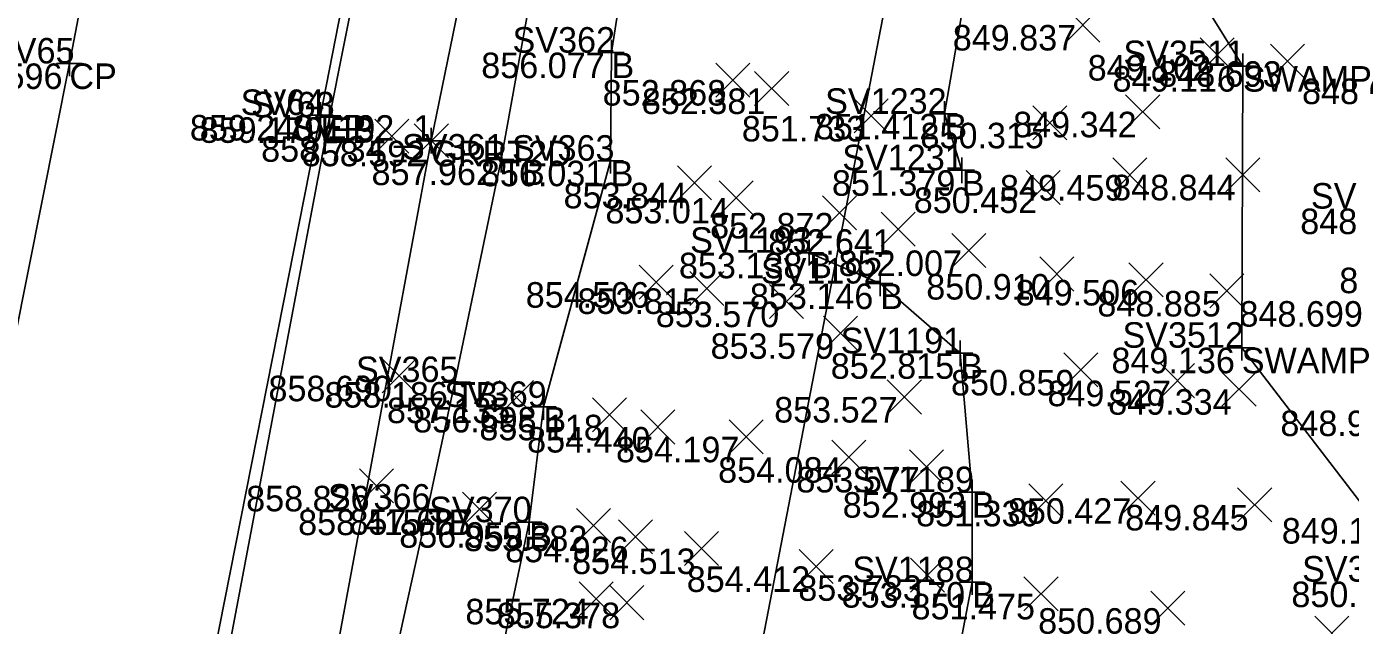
# Model space of a CAD drawing. Extents: x 2228183 to 2230895, y 679226 to 682223.
# Drawn here: x 2228291.3 to 2228343.2, y 680470.3 to 680493.8 of the extents above; entities that cross this region are included whole.
import ezdxf

# ---------------------------------------------------------------- set-up
doc = ezdxf.new("R2010")
doc.units = 0
for name, color, linetype in [('HY_X_Water_Edge', 7, 'Continuous'), ('PV_X_COP', 7, 'Continuous'), ('PV_X_EOP', 7, 'Continuous'), ('PV_X_Shoulder_Aggregate', 7, 'Continuous'), ('RD_X_GR_Rt', 7, 'Continuous'), ('SC_Scratch1', 7, 'Continuous'), ('SV_P_Control_Cells_Set', 7, 'Continuous'), ('SV_X_Break_Lines', 7, 'Continuous'), ('SV_X_Random_Point', 7, 'Continuous'), ('SV_X_Shot_Marker', 7, 'Continuous'), ('SV_X_Text_Comment', 7, 'Continuous'), ('SV_X_Top_of_Bank', 7, 'Continuous'), ('UT_X_Telecom', 7, 'Continuous')]:
    doc.layers.add(name, color=color, linetype=linetype)

msp = doc.modelspace()

# ---------------------------------------------------------------- linework, layer by layer
at = {"layer": 'HY_X_Water_Edge'}
msp.add_lwpolyline([(2228388.587, 680538.705), (2228381.654, 680540.428), (2228373.267, 680534.114), (2228362.534, 680538.041), (2228352.058, 680544.515), (2228344.28, 680554.272), (2228336.684, 680545.185), (2228336.291, 680530.248), (2228335.4, 680519.473), (2228335.533, 680511.573), (2228332.556, 680502.567), (2228338.972, 680492.245), (2228338.927, 680481.209), (2228345.953, 680472.044), (2228352.301, 680471.046)], dxfattribs=at)
at = {"layer": 'PV_X_COP'}
msp.add_lwpolyline([(2228262.604, 680193.524), (2228262.146, 680218.328), (2228262.437, 680243.717), (2228263.104, 680268.902), (2228264.443, 680294.535), (2228266.222, 680319.78), (2228268.589, 680344.685), (2228271.405, 680369.17), (2228274.939, 680394.252), (2228278.914, 680418.584), (2228283.486, 680443.605), (2228288.154, 680467.93), (2228293.014, 680492.349), (2228297.716, 680516.963), (2228302.55, 680541.357), (2228307.231, 680565.55), (2228311.972, 680589.697), (2228316.792, 680614.507), (2228321.818, 680639.234), (2228326.722, 680663.726), (2228331.754, 680688.345)], dxfattribs=at)
at = {"layer": 'PV_X_EOP'}
msp.add_lwpolyline([(2228272.958, 680193.788), (2228272.514, 680218.749), (2228272.761, 680243.66), (2228273.456, 680268.53), (2228274.726, 680293.686), (2228276.435, 680318.586), (2228278.817, 680343.424), (2228281.861, 680368.095), (2228285.158, 680392.512), (2228289.018, 680417.009), (2228293.5, 680441.465), (2228298.055, 680466.05), (2228302.846, 680490.329), (2228307.636, 680514.848), (2228312.366, 680539.332), (2228317.173, 680563.701), (2228322.066, 680588.07), (2228326.883, 680612.686), (2228331.837, 680637.002), (2228336.903, 680661.667), (2228341.796, 680685.984)], dxfattribs=at)
at = {"layer": 'PV_X_Shoulder_Aggregate'}
msp.add_lwpolyline([(2228273.386, 680193.772), (2228272.957, 680218.691), (2228273.264, 680243.644), (2228274.133, 680268.478), (2228275.472, 680293.621), (2228277.239, 680318.511), (2228279.649, 680343.317), (2228282.622, 680367.988), (2228285.854, 680392.371), (2228289.575, 680416.853), (2228293.89, 680441.38), (2228298.61, 680465.949), (2228303.2, 680490.238), (2228308.065, 680514.741), (2228313.026, 680539.169), (2228317.996, 680563.53), (2228322.869, 680587.896), (2228327.71, 680612.549), (2228332.443, 680636.855), (2228337.368, 680661.526), (2228342.398, 680685.817)], dxfattribs=at)
at = {"layer": 'RD_X_GR_Rt'}
msp.add_lwpolyline([(2228290.359, 680391.22), (2228294.274, 680415.932), (2228298.414, 680440.801), (2228302.718, 680465.177), (2228307.188, 680489.321), (2228312.206, 680513.859), (2228316.706, 680538.587), (2228321.519, 680562.878), (2228326.574, 680587.113), (2228331.32, 680611.864), (2228336.079, 680636.156), (2228341.093, 680660.882), (2228346.244, 680685.06), (2228350.849, 680709.572), (2228355.751, 680733.95), (2228357.804, 680743.718), (2228360.585, 680755.706), (2228364.08, 680768.892), (2228368.125, 680781.145)], dxfattribs=at)
at = {"layer": 'SV_X_Break_Lines'}
for points in [[(2228327.962, 680488.164), (2228327.281, 680490.374), (2228328.057, 680494.824), (2228328.274, 680499.17), (2228326.262, 680503.654), (2228325.899, 680506.488), (2228326.476, 680511.569), (2228328.404, 680517.354)], [(2228314.747, 680495.992), (2228314.241, 680492.773), (2228314.211, 680488.538), (2228311.578, 680478.889), (2228311.017, 680474.372), (2228309.793, 680468.535), (2228309.215, 680465.931), (2228309.05, 680463.646), (2228307.936, 680454.458), (2228306.438, 680447.736), (2228305.961, 680443.231)], [(2228324.748, 680453.895), (2228324.393, 680456.839), (2228324.797, 680460.14), (2228327.19, 680465.87), (2228328.374, 680472.025), (2228328.363, 680475.549), (2228327.9, 680480.992), (2228324.768, 680483.725), (2228321.985, 680484.931)]]:
    msp.add_lwpolyline(points, dxfattribs=at)
at = {"layer": 'SV_X_Random_Point'}
for p, q in [((2228332.038, 680493.19), (2228333.372, 680494.525)), ((2228332.038, 680494.525), (2228333.372, 680493.19)), ((2228337.3, 680492.012), (2228338.634, 680493.347)), ((2228337.3, 680493.347), (2228338.634, 680492.012)), ((2228340.054, 680491.769), (2228341.388, 680493.104)), ((2228340.054, 680493.104), (2228341.388, 680491.769)), ((2228318.332, 680491.032), (2228319.666, 680492.367)), ((2228318.332, 680492.367), (2228319.666, 680491.032)), ((2228319.85, 680490.702), (2228321.184, 680492.037)), ((2228319.85, 680492.037), (2228321.184, 680490.702)), ((2228334.38, 680489.789), (2228335.714, 680491.124)), ((2228334.38, 680491.124), (2228335.714, 680489.789)), ((2228323.746, 680489.625), (2228325.08, 680490.96)), ((2228323.746, 680490.96), (2228325.08, 680489.625)), ((2228330.749, 680489.357), (2228332.083, 680490.692)), ((2228330.749, 680490.692), (2228332.083, 680489.357)), ((2228304.979, 680488.83), (2228306.313, 680490.165)), ((2228304.979, 680490.165), (2228306.313, 680488.83)), ((2228306.521, 680488.654), (2228307.855, 680489.989)), ((2228306.521, 680489.989), (2228307.855, 680488.654)), ((2228333.875, 680487.31), (2228335.209, 680488.645)), ((2228333.875, 680488.645), (2228335.209, 680487.31)), ((2228338.306, 680487.319), (2228339.64, 680488.654)), ((2228338.306, 680488.654), (2228339.64, 680487.319)), ((2228316.823, 680487.005), (2228318.157, 680488.34)), ((2228316.823, 680488.34), (2228318.157, 680487.005)), ((2228330.487, 680486.822), (2228331.821, 680488.157)), ((2228330.487, 680488.157), (2228331.821, 680486.822)), ((2228318.462, 680486.412), (2228319.796, 680487.747)), ((2228318.462, 680487.747), (2228319.796, 680486.412)), ((2228322.511, 680485.824), (2228323.845, 680487.159)), ((2228322.511, 680487.159), (2228323.845, 680485.824)), ((2228324.803, 680485.184), (2228326.137, 680486.519)), ((2228324.803, 680486.519), (2228326.137, 680485.184)), ((2228327.569, 680484.353), (2228328.903, 680485.688)), ((2228327.569, 680485.688), (2228328.903, 680484.353)), ((2228315.323, 680483.112), (2228316.657, 680484.447)), ((2228315.323, 680484.447), (2228316.657, 680483.112)), ((2228331.019, 680483.43), (2228332.353, 680484.765)), ((2228331.019, 680484.765), (2228332.353, 680483.43)), ((2228334.51, 680483.197), (2228335.844, 680484.532)), ((2228334.51, 680484.532), (2228335.844, 680483.197)), ((2228317.316, 680482.866), (2228318.65, 680484.201)), ((2228317.316, 680484.201), (2228318.65, 680482.866)), ((2228337.675, 680482.766), (2228339.009, 680484.101)), ((2228337.675, 680484.101), (2228339.009, 680482.766)), ((2228320.427, 680482.348), (2228321.761, 680483.683)), ((2228320.427, 680483.683), (2228321.761, 680482.348)), ((2228322.542, 680481.107), (2228323.876, 680482.442)), ((2228322.542, 680482.442), (2228323.876, 680481.107)), ((2228305.257, 680479.444), (2228306.591, 680480.779)), ((2228305.257, 680480.779), (2228306.591, 680479.444)), ((2228331.957, 680479.673), (2228333.291, 680481.008)), ((2228331.957, 680481.008), (2228333.291, 680479.673)), ((2228335.747, 680479.25), (2228337.081, 680480.585)), ((2228335.747, 680480.585), (2228337.081, 680479.25)), ((2228338.153, 680478.918), (2228339.487, 680480.253)), ((2228338.153, 680480.253), (2228339.487, 680478.918)), ((2228309.854, 680478.586), (2228311.188, 680479.921)), ((2228309.854, 680479.921), (2228311.188, 680478.586)), ((2228325.046, 680478.61), (2228326.38, 680479.945)), ((2228325.046, 680479.945), (2228326.38, 680478.61)), ((2228313.503, 680477.914), (2228314.837, 680479.249)), ((2228313.503, 680479.249), (2228314.837, 680477.914)), ((2228315.387, 680477.434), (2228316.721, 680478.769)), ((2228315.387, 680478.769), (2228316.721, 680477.434)), ((2228318.851, 680477.054), (2228320.185, 680478.389)), ((2228318.851, 680478.389), (2228320.185, 680477.054)), ((2228322.875, 680476.252), (2228324.209, 680477.587)), ((2228322.875, 680477.587), (2228324.209, 680476.252)), ((2228325.915, 680475.871), (2228327.249, 680477.206)), ((2228325.915, 680477.206), (2228327.249, 680475.871)), ((2228304.374, 680475.13), (2228305.708, 680476.465)), ((2228304.374, 680476.465), (2228305.708, 680475.13)), ((2228308.411, 680474.212), (2228309.745, 680475.547)), ((2228308.411, 680475.547), (2228309.745, 680474.212)), ((2228330.59, 680474.543), (2228331.924, 680475.878)), ((2228330.59, 680475.878), (2228331.924, 680474.543)), ((2228334.197, 680474.644), (2228335.531, 680475.979)), ((2228334.197, 680475.979), (2228335.531, 680474.644)), ((2228338.765, 680474.381), (2228340.099, 680475.716)), ((2228338.765, 680475.716), (2228340.099, 680474.381)), ((2228312.87, 680473.57), (2228314.204, 680474.905)), ((2228312.87, 680474.905), (2228314.204, 680473.57)), ((2228314.52, 680473.135), (2228315.854, 680474.47)), ((2228314.52, 680474.47), (2228315.854, 680473.135)), ((2228317.1, 680472.674), (2228318.434, 680474.009)), ((2228317.1, 680474.009), (2228318.434, 680472.674)), ((2228321.597, 680471.972), (2228322.931, 680473.307)), ((2228321.597, 680473.307), (2228322.931, 680471.972)), ((2228325.958, 680471.624), (2228327.292, 680472.959)), ((2228325.958, 680472.959), (2228327.292, 680471.624)), ((2228312.977, 680470.703), (2228314.311, 680472.038)), ((2228312.977, 680472.038), (2228314.311, 680470.703)), ((2228314.183, 680470.551), (2228315.517, 680471.886)), ((2228314.183, 680471.886), (2228315.517, 680470.551)), ((2228330.399, 680470.898), (2228331.733, 680472.233)), ((2228330.399, 680472.233), (2228331.733, 680470.898)), ((2228335.37, 680470.335), (2228336.704, 680471.67)), ((2228335.37, 680471.67), (2228336.704, 680470.335)), ((2228341.786, 680469.35), (2228343.12, 680470.685)), ((2228341.786, 680470.685), (2228343.12, 680469.35))]:
    msp.add_line(p, q, dxfattribs=at)
at = {"layer": 'SV_X_Shot_Marker'}
for p, q in [((2228314.241, 680493.273), (2228314.241, 680492.273)), ((2228293.014, 680492.849), (2228293.014, 680491.849)), ((2228313.741, 680492.773), (2228314.741, 680492.773)), ((2228314.241, 680492.773), (2228314.241, 680492.773)), ((2228338.972, 680492.745), (2228338.972, 680491.745)), ((2228292.514, 680492.349), (2228293.514, 680492.349)), ((2228293.014, 680492.349), (2228293.014, 680492.349)), ((2228338.472, 680492.245), (2228339.472, 680492.245)), ((2228338.972, 680492.245), (2228338.972, 680492.245)), ((2228302.846, 680490.829), (2228302.846, 680489.829)), ((2228303.2, 680490.738), (2228303.2, 680489.738)), ((2228327.281, 680490.874), (2228327.281, 680489.874)), ((2228302.346, 680490.329), (2228303.346, 680490.329)), ((2228302.7, 680490.238), (2228303.7, 680490.238)), ((2228302.846, 680490.329), (2228302.846, 680490.329)), ((2228303.2, 680490.238), (2228303.2, 680490.238)), ((2228326.781, 680490.374), (2228327.781, 680490.374)), ((2228327.281, 680490.374), (2228327.281, 680490.374)), ((2228307.188, 680489.821), (2228307.188, 680488.821)), ((2228306.688, 680489.321), (2228307.688, 680489.321)), ((2228307.188, 680489.321), (2228307.188, 680489.321)), ((2228309.921, 680489.081), (2228309.921, 680488.081)), ((2228314.211, 680489.038), (2228314.211, 680488.038)), ((2228309.421, 680488.581), (2228310.421, 680488.581)), ((2228309.921, 680488.581), (2228309.921, 680488.581)), ((2228313.711, 680488.538), (2228314.711, 680488.538)), ((2228314.211, 680488.538), (2228314.211, 680488.538)), ((2228327.962, 680488.664), (2228327.962, 680487.664)), ((2228327.462, 680488.164), (2228328.462, 680488.164)), ((2228327.962, 680488.164), (2228327.962, 680488.164)), ((2228321.985, 680485.431), (2228321.985, 680484.431)), ((2228321.485, 680484.931), (2228322.485, 680484.931)), ((2228321.985, 680484.931), (2228321.985, 680484.931)), ((2228324.768, 680484.225), (2228324.768, 680483.225)), ((2228324.268, 680483.725), (2228325.268, 680483.725)), ((2228324.768, 680483.725), (2228324.768, 680483.725)), ((2228327.9, 680481.492), (2228327.9, 680480.492)), ((2228338.927, 680481.709), (2228338.927, 680480.709)), ((2228327.4, 680480.992), (2228328.4, 680480.992)), ((2228327.9, 680480.992), (2228327.9, 680480.992)), ((2228338.427, 680481.209), (2228339.427, 680481.209)), ((2228338.927, 680481.209), (2228338.927, 680481.209)), ((2228308.107, 680480.363), (2228308.107, 680479.363)), ((2228307.607, 680479.863), (2228308.607, 680479.863)), ((2228308.107, 680479.863), (2228308.107, 680479.863)), ((2228311.578, 680479.389), (2228311.578, 680478.389)), ((2228311.078, 680478.889), (2228312.078, 680478.889)), ((2228311.578, 680478.889), (2228311.578, 680478.889)), ((2228328.363, 680476.049), (2228328.363, 680475.049)), ((2228327.863, 680475.549), (2228328.863, 680475.549)), ((2228328.363, 680475.549), (2228328.363, 680475.549)), ((2228307.043, 680475.364), (2228307.043, 680474.364)), ((2228306.543, 680474.864), (2228307.543, 680474.864)), ((2228307.043, 680474.864), (2228307.043, 680474.864)), ((2228311.017, 680474.872), (2228311.017, 680473.872)), ((2228310.517, 680474.372), (2228311.517, 680474.372)), ((2228311.017, 680474.372), (2228311.017, 680474.372)), ((2228328.374, 680472.525), (2228328.374, 680471.525)), ((2228327.874, 680472.025), (2228328.874, 680472.025)), ((2228328.374, 680472.025), (2228328.374, 680472.025))]:
    msp.add_line(p, q, dxfattribs=at)
at = {"layer": 'SV_X_Top_of_Bank'}
msp.add_lwpolyline([(2228313.24, 680508.044), (2228312.693, 680504.139), (2228311.655, 680498.217), (2228309.921, 680488.581), (2228308.107, 680479.863), (2228307.043, 680474.864), (2228305.815, 680469.295), (2228305.987, 680466.983), (2228305.966, 680464.279), (2228304.125, 680455.586), (2228302.925, 680448.672), (2228301.763, 680443.689), (2228300.838, 680439.938), (2228299.782, 680433.077), (2228298.614, 680423.72), (2228298.016, 680421.452), (2228298.283, 680417.737), (2228297.819, 680415.042)], dxfattribs=at)
at = {"layer": 'UT_X_Telecom'}
msp.add_lwpolyline([(2228306.801, 680400.49), (2228337.511, 680559.672), (2228349.317, 680620.055), (2228359.383, 680671.523), (2228365.58, 680702.692), (2228381.421, 680781.425)], dxfattribs=at)

# ---------------------------------------------------------------- texts
at = {"layer": 'SC_Scratch1'}
for s, p in [('849.837', (2228327.609, 680492.857)), ('856.077', (2228309.145, 680491.773)), ('849.102', (2228332.894, 680491.679)), ('859.596', (2228287.91, 680491.349)), ('849.116', (2228333.868, 680491.245)), ('848.693', (2228335.657, 680491.436)), ('852.868', (2228313.899, 680490.699)), ('848.630', (2228341.287, 680490.756)), ('852.381', (2228315.435, 680490.369)), ('859.240', (2228297.732, 680489.329)), ('859.179', (2228298.116, 680489.238)), ('851.733', (2228319.349, 680489.292)), ('851.412', (2228322.208, 680489.374)), ('850.315', (2228326.346, 680489.024)), ('849.342', (2228329.974, 680489.456)), ('858.734', (2228300.524, 680488.497)), ('858.592', (2228302.115, 680488.321)), ('858.592', (2228302.115, 680488.321)), ('857.962', (2228304.848, 680487.581)), ('856.031', (2228309.129, 680487.538)), ('851.379', (2228322.878, 680487.164)), ('849.459', (2228329.458, 680486.977)), ('848.844', (2228333.851, 680486.986)), ('853.844', (2228312.368, 680486.672)), ('850.452', (2228326.081, 680486.489)), ('853.014', (2228314.007, 680486.079)), ('852.872', (2228318.105, 680485.491)), ('848.501', (2228341.218, 680485.661)), ('852.641', (2228320.388, 680484.851)), ('853.138', (2228316.885, 680483.931)), ('852.007', (2228323.14, 680484.02)), ('848.271', (2228342.748, 680483.346)), ('850.910', (2228326.572, 680483.097)), ('849.506', (2228330.073, 680482.864)), ('854.506', (2228310.886, 680482.779)), ('853.815', (2228312.913, 680482.533)), ('853.146', (2228319.664, 680482.725)), ('848.885', (2228333.272, 680482.433)), ('853.570', (2228315.98, 680482.015)), ('848.699', (2228338.836, 680482.035)), ('853.579', (2228318.125, 680480.774)), ('849.136', (2228333.823, 680480.209)), ('852.815', (2228322.83, 680479.992)), ('850.859', (2228327.54, 680479.34)), ('858.690', (2228300.81, 680479.111)), ('858.186', (2228303.003, 680478.863)), ('849.527', (2228331.318, 680478.917)), ('857.135', (2228305.451, 680478.253)), ('853.527', (2228320.617, 680478.277)), ('849.334', (2228333.698, 680478.585)), ('856.698', (2228306.478, 680477.889)), ('848.939', (2228340.44, 680477.747)), ('855.118', (2228309.07, 680477.581)), ('854.440', (2228310.94, 680477.101)), ('854.197', (2228314.422, 680476.721)), ('854.084', (2228318.42, 680475.919)), ('853.577', (2228321.486, 680475.538)), ('858.826', (2228299.937, 680474.797)), ('852.993', (2228323.299, 680474.549)), ('851.339', (2228326.173, 680474.21)), ('850.427', (2228329.768, 680474.311)), ('849.845', (2228334.362, 680474.048)), ('858.415', (2228301.973, 680473.864)), ('857.687', (2228303.982, 680473.879)), ('849.188', (2228340.495, 680473.534)), ('856.959', (2228305.933, 680473.372)), ('855.382', (2228308.464, 680473.237)), ('854.926', (2228310.083, 680472.802)), ('854.513', (2228312.703, 680472.341)), ('854.412', (2228317.191, 680471.639)), ('853.783', (2228321.561, 680471.291)), ('853.170', (2228323.26, 680471.025)), ('850.181', (2228340.871, 680471.044)), ('855.724', (2228308.522, 680470.37)), ('851.475', (2228325.996, 680470.565)), ('855.378', (2228309.75, 680470.218)), ('850.689', (2228330.953, 680470.002))]:
    msp.add_text(s, height=1, dxfattribs=at).set_placement(p)
at = {"layer": 'SV_P_Control_Cells_Set'}
for s, p in [('SV362', (2228310.368, 680492.773)), ('SV65', (2228289.942, 680492.349)), ('SV3511', (2228334.292, 680492.245)), ('SV64', (2228299.722, 680490.329)), ('SV63', (2228300.134, 680490.238)), ('SV1232', (2228322.61, 680490.374)), ('SV192_1', (2228301.723, 680489.321)), ('SV361', (2228306.039, 680488.581)), ('SV363', (2228310.347, 680488.538)), ('SV1231', (2228323.282, 680488.164)), ('SV1013', (2228341.638, 680486.661)), ('SV1193', (2228317.323, 680484.931)), ('SV1192', (2228320.097, 680483.725)), ('SV1191', (2228323.22, 680480.992)), ('SV3512', (2228334.256, 680481.209)), ('SV365', (2228304.237, 680479.863)), ('SV369', (2228307.694, 680478.889)), ('SV1189', (2228323.681, 680475.549)), ('SV366', (2228303.139, 680474.864)), ('SV370', (2228307.103, 680474.372)), ('SV1188', (2228323.675, 680472.025)), ('SV3513', (2228341.291, 680472.044))]:
    msp.add_text(s, height=1, dxfattribs=at).set_placement(p)
at = {"layer": 'SV_X_Text_Comment'}
for s, p in [('B', (2228314.241, 680491.773)), ('CP', (2228293.014, 680491.349)), ('SWAMP', (2228338.972, 680491.245)), ('EP', (2228302.846, 680489.329)), ('EB', (2228303.2, 680489.238)), ('B', (2228327.281, 680489.374)), ('GRRT2D', (2228307.188, 680488.321)), ('TB', (2228309.921, 680487.581)), ('B', (2228314.211, 680487.538)), ('B', (2228327.962, 680487.164)), ('B', (2228321.985, 680483.931)), ('B', (2228324.768, 680482.725)), ('SWAMP', (2228338.927, 680480.209)), ('B', (2228327.9, 680479.992)), ('TB', (2228308.107, 680478.863)), ('B', (2228311.578, 680477.889)), ('B', (2228328.363, 680474.549)), ('TB', (2228307.043, 680473.864)), ('B', (2228311.017, 680473.372)), ('B', (2228328.374, 680471.025))]:
    msp.add_text(s, height=1, dxfattribs=at).set_placement(p)

doc.saveas('drawing.dxf')
